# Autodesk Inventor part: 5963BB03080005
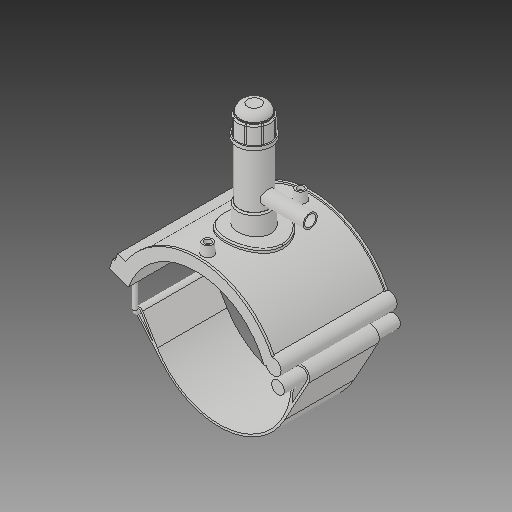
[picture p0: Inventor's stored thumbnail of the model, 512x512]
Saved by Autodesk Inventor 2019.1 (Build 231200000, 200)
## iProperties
Created: 2017-07
Part Number: 5963BB03080005
Material: Generic
Description: PLASSON TAPPING SADDLE 8''IPS x 1 1/2''IPS
Document SubType Name: Modeling
Designer: KIM
Mass: 1712.7 g
Surface Area: 2671.49 cm^2
Volume: 1712.7 cm^3
Density: 1 g/cm^3
Appearance: Default
Author: KIM
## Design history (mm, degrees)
derived "5963B.ipt"
feature "Solid1::5963B.ipt"
feature "Solid2::5963B.ipt"
feature "Solid4::5963B.ipt"
feature "Solid5::5963B.ipt"
tag "TaggingFeature1" dims "d_" = 218.7
body "Solid1"
body "Solid2"
other parameters: "B_" = 179.832, "L_" = 176.022, "d_t" = 6, "H_2" = 177.038, "H_1" = 65.024, "d_1" = 21.2, "H_" = 85.09, "d1" = 249.318, "d148" = 3.2805, "d160" = 3.2805, "d169" = 3.2805, "d192" = 6.1236, "d0" = 218.7, "d2" = 269.748, "d3" = 54.675, "d4" = 176.022, "d5" = 0, "d6" = 0.1, "d8" = 0, "d19" = 6, "d20" = 6, "d21" = 105.6132, "d23" = 0, "d24" = 52.8066, "d26" = 0, "d29" = 3, "d30" = 72.9, "d31" = 6, "d32" = 0, "d33" = 0, "d34" = 0.6, "d40" = 129.64536, "d41" = 87.48, "d43" = 0, "d45" = 0, "d47" = 230.2722, "d70" = 15, "d72" = 0, "d73" = 6, "d75" = 5, "d76" = 0, "d77" = 10.935, "d78" = 139.35, "d79" = 15, "d80" = 70.4088, "d82" = 5 deg, "d84" = 4, "d85" = 14, "d86" = 0, "d87" = 3, "d88" = 0, "d89" = 1, "d90" = 1, "d91" = 140.8176, "d92" = 0, "d93" = 0.5, "d94" = 115.10526, "d96" = 254.30436, "d97" = 3.52044, "d98" = 0, "d102" = 2.187, "d120" = 140 deg, "d121" = 24.228, "d122" = 20 deg, "d123" = 498.636, "d124" = 149.5908, "d126" = 0, "d143" = 225.261, "d145" = 23.55231, "d149" = 3.2805, "d150" = 25.90754, "d153" = 176.022, "d154" = 0, "d156" = 124.659, "d157" = 160 deg, "d159" = 6.1236, "d161" = 3.2805, "d162" = 105.6132, "d163" = 0, "d164" = 109.35, "d167" = 21.87, "d168" = 121.61854, "d170" = 3.2805, "d172" = 0, "d173" = 1, "d175" = 109.35, "d176" = 20 deg, "d177" = 15.309, "d178" = 30.618, "d180" = 0, "d183" = 12.2472, "d184" = 12.2472, "d185" = 57.20715, "d186" = 57.20715, "d187" = 124.659, "d188" = 9.1854, "d189" = 15.309, "d190" = 0, "d191" = 186.9885, "d193" = 6.1236, "d194" = 6.16077, "d195" = 90 deg, "d197" = 0, "d199" = 0, "d200" = 15.309, "d202" = 0, "d203" = 177.038, "d204" = 49.8636, "d205" = 36.7416, "d206" = 44.6148, "d207" = 132.7785, "d208" = 138.08964, "d209" = 164.64534, "d210" = 45.13968, "d211" = 52.488, "d212" = 41.9904, "d213" = 48.9816, "d216" = 0, "d217" = 21.87, "d218" = 10.935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
